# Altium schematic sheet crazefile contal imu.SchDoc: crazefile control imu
size A4; CompanyName: 良工作室; DrawnBy: 郑良杰; Engineer: 郑良杰; Organization: 良工作室; DocumentNumber: 2; SheetNumber: 2; SheetTotal: 4
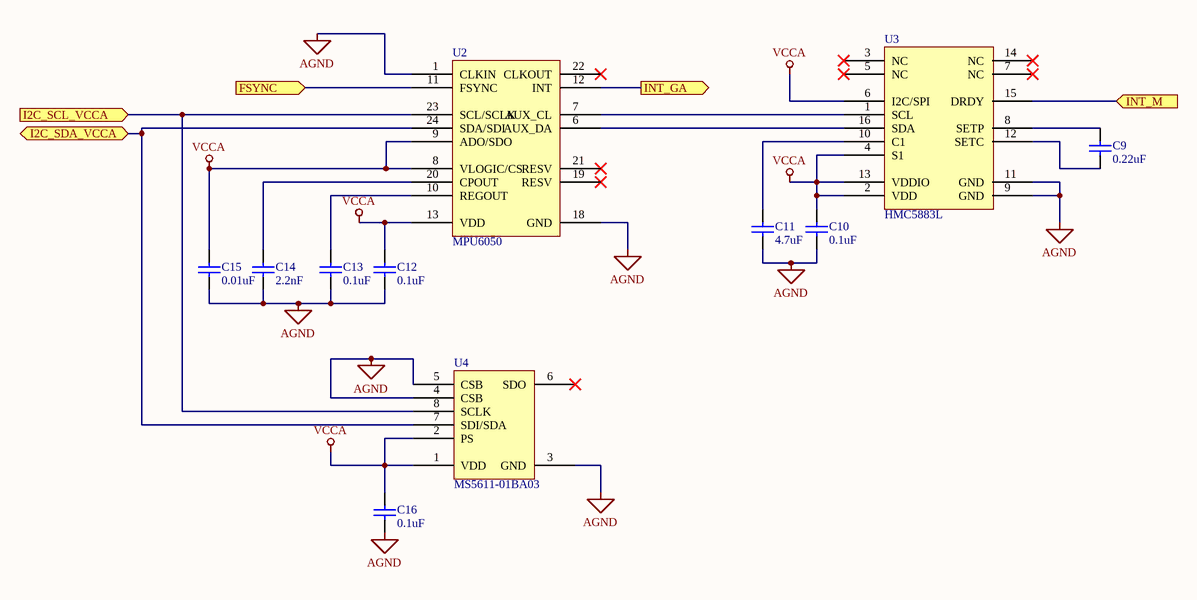
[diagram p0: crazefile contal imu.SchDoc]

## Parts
C9  value 0.22uF  [CAP_0603]  (hidden comment: Cap)
C10  value 0.1uF  [CAP_0603]  (hidden comment: Cap)
C11  value 4.7uF  [CAP_0603]  (hidden comment: Cap)
C12  value 0.1uF  [CAP_0603]  (hidden comment: Cap)
C13  value 0.1uF  [CAP_0603]  (hidden comment: Cap)
C14  value 2.2nF  [CAP_0603]  (hidden comment: Cap)
C15  value 0.01uF  [CAP_0603]  (hidden comment: Cap)
C16  value 0.1uF  [CAP_0603]  (hidden comment: Cap)
U2  MPU6050  [MPU9150]
U3  HMC5883L  [HMC5883L]
U4  MS5611-01BA03  [FQN8]

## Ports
FSYNC (in), I2C_SCL_VCCA (in), I2C_SDA_VCCA, INT_GA (out), INT_M (in)

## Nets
AGND: C10.1 C11.1 C12.2 C13.1 C14.1 C15.1 C16.1 U2.1(CLKIN) U2.18(GND) U3.9(GND) U3.11(GND) U4.3(GND) U4.4(CSB) U4.5(CSB)
VCCA: C10.2 C12.1 C15.2 C16.2 U2.8(VLOGIC/CS) U2.9(ADO/SDO) U2.13(VDD) U3.2(VDD) U3.4(S1) U3.6(I2C/SPI) U3.13(VDDIO) U4.1(VDD) U4.2(PS)
FSYNC: U2.11(FSYNC) ; port FSYNC
I2C_SCL_VCCA: U2.23(SCL/SCLK) U4.8(SCLK) ; port I2C_SCL_VCCA
I2C_SDA_VCCA: U2.24(SDA/SDI) U4.7(SDI/SDA) ; port I2C_SDA_VCCA
INT_GA: U2.12(INT) ; port INT_GA
INT_M: U3.15(DRDY) ; port INT_M
NetC9_1: C9.1 U3.12(SETC)
NetC9_2: C9.2 U3.8(SETP)
NetC11_2: C11.2 U3.10(C1)
NetC13_2: C13.2 U2.10(REGOUT)
NetC14_2: C14.2 U2.20(CPOUT)
NetU2_6: U2.6(AUX_DA) U3.16(SDA)
NetU2_7: U2.7(AUX_CL) U3.1(SCL)

Not connected (* = marked no-connect by the designer): U2 2(NC) 3(NC) 4(NC) 5(NC) 14(NC) 15(NC) 16(NC) 17(NC) 19(RESV)* 21(RESV)* 22(CLKOUT)*; U3 3(NC)* 5(NC)* 7(NC)* 14(NC)*; U4 6(SDO)*

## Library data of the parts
C9-C16 = Cap: Capacitor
